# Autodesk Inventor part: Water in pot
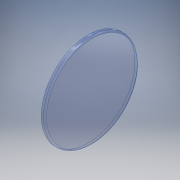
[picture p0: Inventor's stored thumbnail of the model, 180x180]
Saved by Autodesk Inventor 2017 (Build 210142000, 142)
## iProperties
Created: 2020-03
Part Number: Water in pot
Material: Water
Document SubType Name: Modeling
Designer: user
Density: 0.9983 g/cm^3
Appearance: Tropical Blue
Author: user
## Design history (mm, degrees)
sketch "Sketch1"
  geometry: L1 (3, 0)-(8, 0); L2 (8, 0)-(8, -98); L3 (0, -98)-(0, -3); L4 (8, -98)-(0, -98); A1 r 3 centre (3, -3) between (3, 0) and (0, -3); 1 further point
  constraints: 8 end point, 2 point on circle, 2 point on line, 2 tangent, 1 centre point, 1 horizontal, 1 perpendicular
  dimensions: "d0" = 8 distance of point (0, 0) L1.end; "d2" = 3 radius of A1; "d4" = 98 distance between parallel lines of L4 L1
revolve "Revolution1" sketch "Sketch1" stored, may be unused: angle "d3" = 90 deg
body "Solid1"
